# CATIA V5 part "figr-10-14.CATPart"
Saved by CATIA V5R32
Part number: Part1
Bounding box of the stored display mesh (mm): x 0 to 0, y 0 to 59.085, z 0 to 150
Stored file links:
  D:\PROJECTS\Project 2022\CATIA V5 6R 2022\Resources\Part Files\c10_catia_v5_6r2022_prt\c10_catia_v5_6r2022_prt\figr-10-14.CATPart
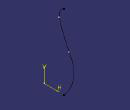
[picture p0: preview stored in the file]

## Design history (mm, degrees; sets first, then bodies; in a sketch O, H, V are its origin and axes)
Set1
  Sketch1 on yz-plane, origin (0, 0, 0), H (0, 1, 0), V (0, 0, 1)
    arc A1 centre (219.5293, 176.8574) radius 194.8379 from (50.3627, 80.1907) to (30.3627, 130.1907) cw
    arc A2 centre (-7.8186, 46.9443) radius 67.0103 from (50.3627, 80.1907) to (40, 0) cw
    arc A3 centre (47.0688, 134.312) radius 17.207 from (30.3627, 130.1907) to (40, 150) cw
    axis line L1 (0, 156.5671) -> (0, -24.1442)
    vertical: L1 V
  Revol1: Element1 Sketch1, Angle1 -60
Body1 (main body)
